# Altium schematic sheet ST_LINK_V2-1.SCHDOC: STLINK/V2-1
size A4; DocumentNumber: MB1180; Revision: C.1; SheetNumber: 3; SheetTotal: 3; Project: NUCLEO32
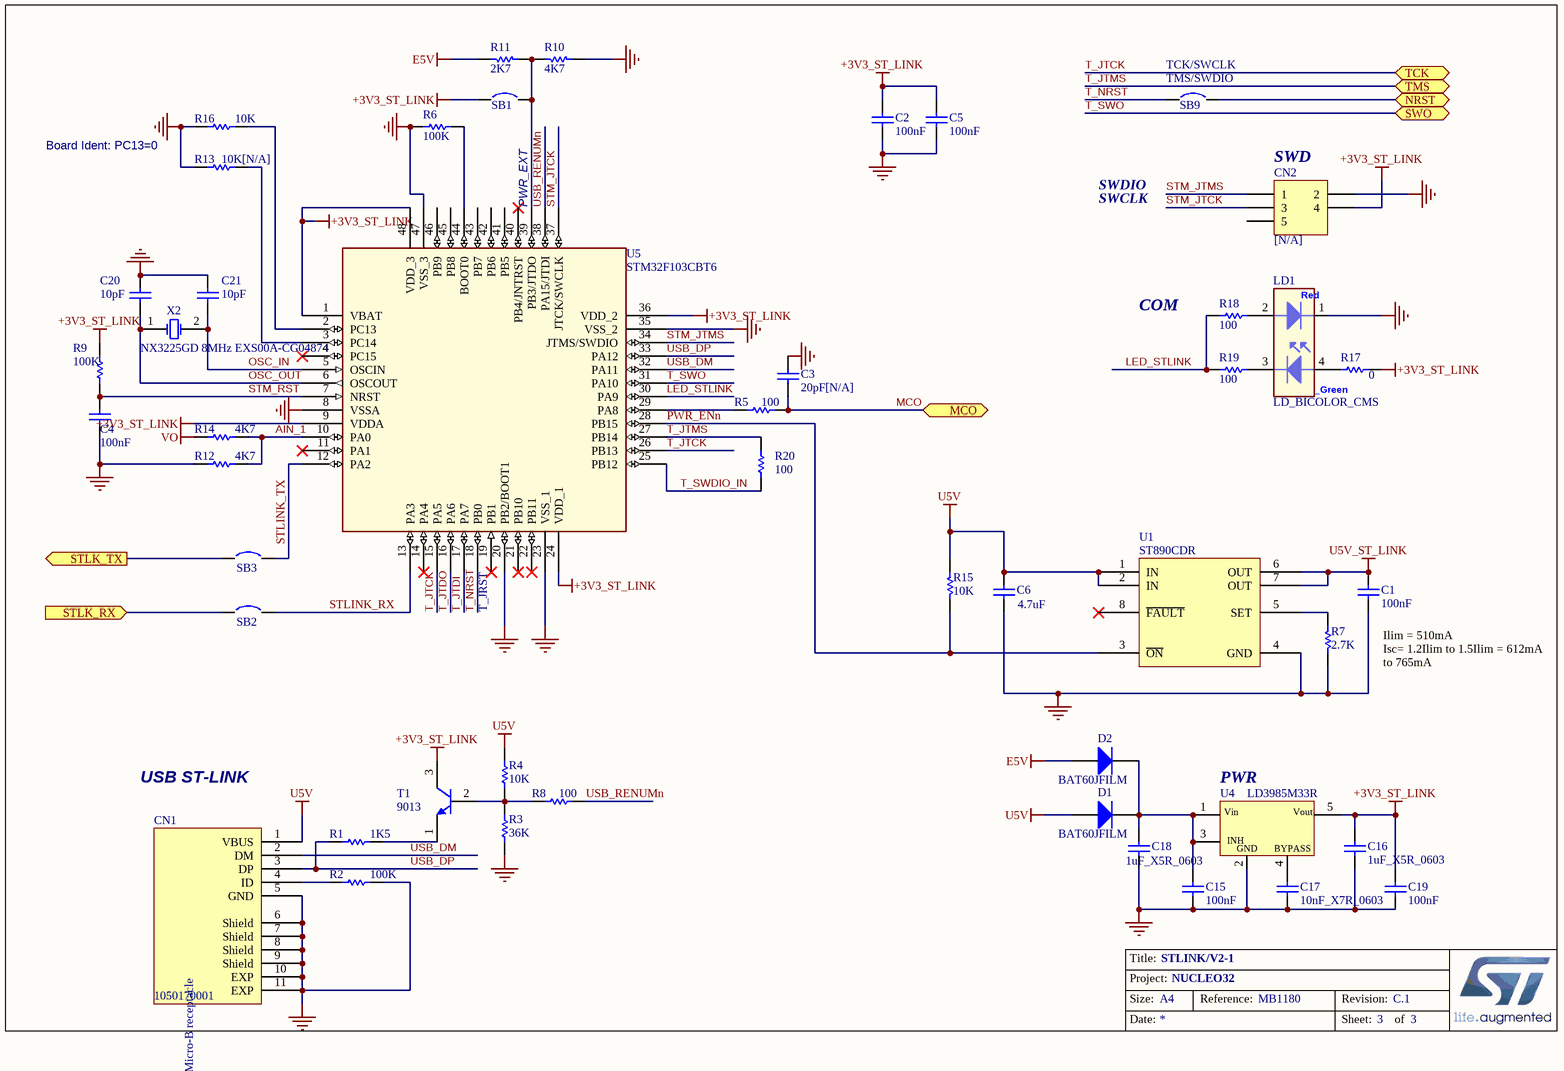
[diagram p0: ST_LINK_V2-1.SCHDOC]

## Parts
C1  100nF  [0603C]
C2  100nF  [0603C]
C3  20pF[N/A]  [0603C]
C4  100nF  [0603C]
C5  100nF  [0603C]
C6  4.7uF  [0603C]
C15  100nF  [0603C]
C16  1uF_X5R_0603  [0603C]
C17  10nF_X7R_0603  [0603C]
C18  1uF_X5R_0603  [0603C]
C19  100nF  [0603C]
C20  10pF  [0603C]
C21  10pF  [0603C]
CN1  1050170001  [Molex_1050170001]
CN2  [N/A]  [HDR_1x5_2R54_V_M]
D1  BAT60JFILM  [SOD-323]
D2  BAT60JFILM  [SOD-323]
LD1  LD_BICOLOR_CMS  [HSMF-A201]
R1  1K5  [0603R]
R2  100K  [0603R]
R3  36K  [0603R]
R4  10K  [0603R]
R5  100  [0603R]
R6  100K  [0603R]
R7  2.7K  [0603R]
R8  100  [0603R]
R9  100K  [0603R]
R10  4K7  [0603R]
R11  2K7  [0603R]
R12  4K7  [0603R]
R13  10K[N/A]  [0603R]
R14  4K7  [0603R]
R15  10K  [0603R]
R16  10K  [0603R]
R17  0  [0603R]
R18  100  [0603R]
R19  100  [0603R]
R20  100  [0603R]
SB1  Circuit Breaker (open)  [SB_0603]  (value not drawn)
SB2  Circuit Breaker (close)  [SB_0603]  (value not drawn)
SB3  Circuit Breaker (close)  [SB_0603]  (value not drawn)
SB9  Circuit Breaker (close)  [SB_0603]  (value not drawn)
T1  9013  [SOT23-3]
U1  ST890CDR  [SO-8]
U4  LD3985M33R  [SOT23-5L]
U5  STM32F103CBT6  [LQFP48_0R5_7x7]
X2  NX3225GD 8MHz EXS00A-CG04874  [XTAL_2SM_3R2x2R5]

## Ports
MCO, NRST, STLK_RX (in), STLK_TX (out), SWO, TCK, TMS

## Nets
+3V3_ST_LINK: C2.2 C5.2 C16.1 C19.2 CN2.4 R9.2 R17.2 SB1.1 T1.3(C) U4.5(Vout) U5.1(VBAT) U5.9(VDDA) U5.24(VDD_1) U5.36(VDD_2) U5.48(VDD_3)
E5V: D2.1(A) R11.1
GND: C1.1 C2.1 C3.2 C4.1 C5.1 C6.1 C15.1 C16.2 C17.1 C18.1 C19.1 C20.2 C21.2 CN1.5(GND) CN1.6(Shield) CN1.7(Shield) CN1.8(Shield) CN1.9(Shield) CN1.10(EXP) CN1.11(EXP) CN2.2 LD1.1 R2.2 R3.1 R6.1 R7.2 R10.2 R12.1 R13.1 R16.1 U1.4(GND) U4.2(GND) U5.8(VSSA) U5.20(PB2/BOOT1) U5.23(VSS_1) U5.35(VSS_2) U5.47(VSS_3)
U5V: C6.2 CN1.1(VBUS) D1.1(A) R4.2 R15.1 U1.1(IN) U1.2(IN)
U5V_ST_LINK: C1.2 U1.6(OUT) U1.7(OUT)
VO: R14.1
AIN_1: R12.2 R14.2 U5.10(PA0)
LED_STLINK: R18.1 R19.1 U5.30(PA9)
MCO: C3.1 R5.2 ; port MCO
NRST: SB9.2 ; port NRST
OSC_IN: C21.1 U5.5(OSCIN) X2.2(OSC2)
OSC_OUT: C20.1 U5.6(OSCOUT) X2.1(OSC1)
PWR_ENn: R15.2 U1.3(~{ON}) U5.28(PB15)
STLINK_RX: SB2.2 U5.13(PA3)
STLINK_TX: SB3.2 U5.12(PA2)
STLK_RX: SB2.1 ; port STLK_RX
STLK_TX: SB3.1 ; port STLK_TX
STM_JTCK: CN2.3 U5.37(JTCK/SWCLK)
STM_JTMS: CN2.1 U5.34(JTMS/SWDIO)
STM_RST: C4.2 R9.1 U5.7(NRST)
T_JTCK: U5.15(PA5) U5.26(PB13) ; port TCK
T_JTDI: U5.17(PA7)
T_JTDO: U5.16(PA6)
T_JTMS: R20.2 U5.27(PB14) ; port TMS
T_NRST: SB9.1 U5.18(PB0)
T_SWDIO_IN: R20.1 U5.25(PB12)
T_SWO: U5.31(PA10) ; port SWO
USB_DM: CN1.2(DM) U5.32(PA11)
USB_DP: CN1.3(DP) R1.1 U5.33(PA12)
USB_RENUMn: R8.2 U5.38(PA15/JTDI)
NetC15_2: C15.2 C18.2 D1.2(K) D2.2(K) U4.1(Vin) U4.3(CE)
NetC17_2: C17.2 U4.4(BYPASS)
NetCN1_4: CN1.4(ID) R2.1
NetLD1_2: LD1.2 R18.2
NetLD1_3: LD1.3 R19.2
NetLD1_4: LD1.4 R17.1
NetR1_2: R1.2 T1.1(E)
NetR3_2: R3.2 R4.1 R8.1 T1.2(B)
NetR5_1: R5.1 U5.29(PA8)
NetR6_2: R6.2 U5.44(BOOT0)
NetR7_1: R7.1 U1.5(SET)
NetR10_1: R10.1 R11.2 SB1.2 U5.39(PB3/JTDO)
NetR13_2: R13.2 U5.3(PC14)
NetR16_2: R16.2 U5.2(PC13)

Not connected (* = marked no-connect by the designer): CN2 5; U1 8(~{FAULT})*; U5 4(PC15)* 11(PA1)* 14(PA4)* 19(PB1)* 21(PB10)* 22(PB11)* 40(PB4/JNTRST)* 41(PB5) 42(PB6) 43(PB7) 45(PB8) 46(PB9)

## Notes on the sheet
- (near SB9) TCK/SWCLK
- (near SB9) TMS/SWDIO
- Board Ident: PC13=0
- (near CN2) SWD
- (near U5) PWR_EXT
- SWCLK
- SWDIO
- COM
- (near U5) T_JRST
- (near C1) Ilim = 510mA
  Isc= 1.2Ilim to 1.5Ilim = 612mA to 765mA
- USB ST-LINK
- (near U4) PWR

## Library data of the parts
C1 C2 C4 C5 C15 C19 = Capacitor_ST: Capacitor 0402 / 0603 / 0805
C3 C20 C21 = Capacitor_ST: Capacitor 0402 / 0603 / 0805; Value: 100nF
C6 C16 C18 = CAP SMD 0603  X5R 1µF 25V 10%: 0603  X5R 1µF; Rated voltage: 25V; Tolerance: 10%
C17 = CAP SMD 0603  X7R 10000PF 50V 10%: 0603  X7R 10NF; Order code RS: 2040779; Rated voltage: 50V; Tolerance: 10%
CN1 = 1050170001: Silkscreen: USB
CN2 = Header 3X2: Header, 3-Pin, Dual row
D1 D2 = BAT60JFILM: Manuf_1: STM; Provided: ST; ECCN_US/EU: EAR99/NEC
LD1 = LD_BICOLOR_CMS: Bicolor Led; Manuf_Part_1: HSMF-A201-A00J1; Manuf_1: Avago Technologies; Ref St: xxxxxx; cap_dec: ----
R1 R2 R5 R6 R8 R9 R17-R20 = Resistor_ST: Resistor 0402 / 0603 / 0805; Description: Resistor 0402 or 0603 or 0805; Value: 10K
R3 R4 R10 R11 = Res1: Resistor; Value: 1K
R7 R15 = Res1: Resistor; Value: 1K; Ordered by: Subcon
R12-R14 = Resistor_ST: Resistor 0402 / 0603 / 0805; Description: Resistor 0402 or 0603 or 0805; Value: 10K; Fitted: NO
R16 = Resistor_ST: Resistor 0402 / 0603 / 0805; Description: Resistor 0402 or 0603 or 0805
SB1-SB3 SB9 = Circuit Breaker: Solder: NO
T1 = NPN: NPN Bipolar Transistor; Code - JEDEC: TO-226-AA
U4 = LD3985M33R: Ultra low drop-low noise BiCMOS voltage, regulators low ESR capacitors compatible; Manuf_1: STM; Provided: ST; Ref St: 9176161; ECCN_US/EU: EAR99/NEC
U5 = STM32F103CBT6: Medium-density performance line ARM-based 32-bit MCU with 64KB Flash; Manuf_Part_1: STM32F103C8T6; Manuf_1: STM; Ref St: 9175981; Provided: ST; ECCN_US/EU: 3A991A2/NEC
X2 = XTAL: Crystal Oscillator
